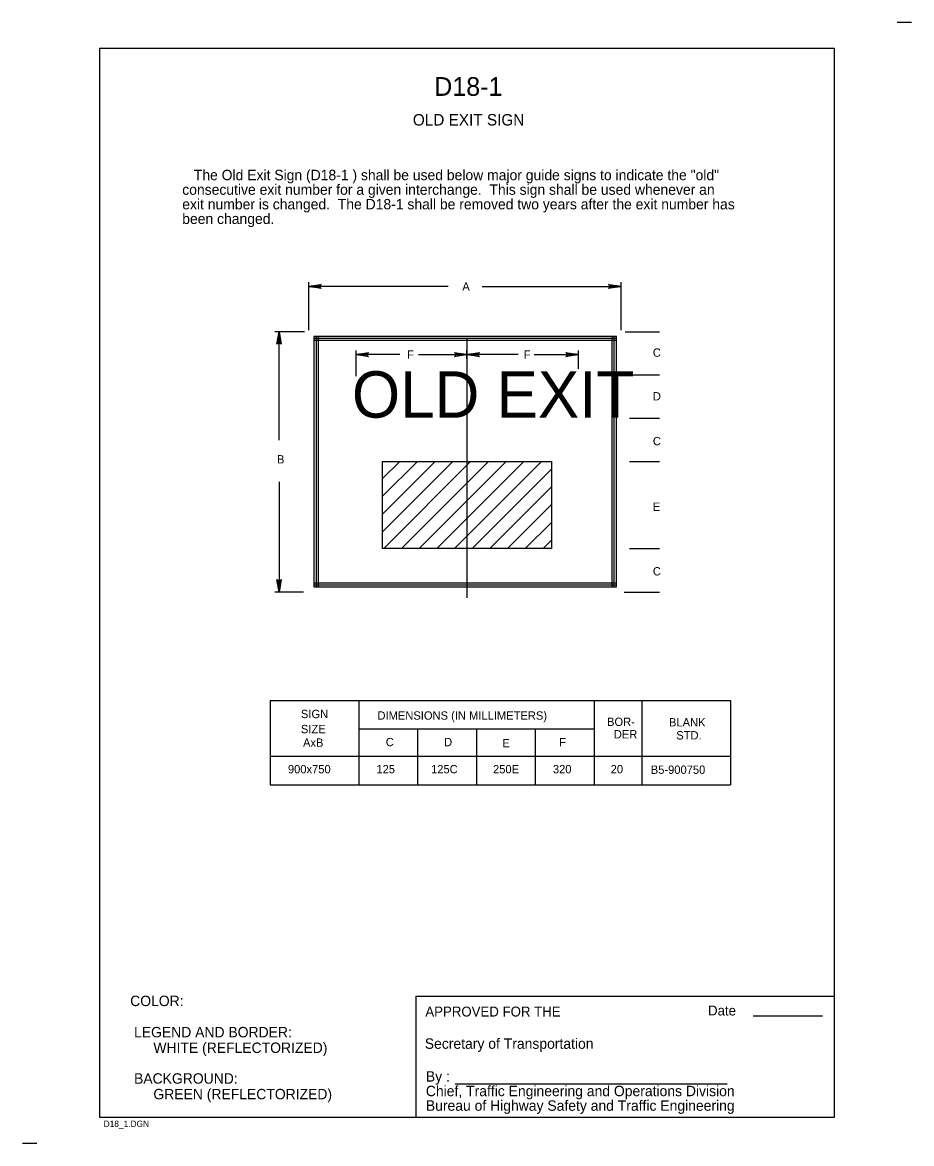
# Model space of a CAD drawing. Extents: x -0.018 to 0.195, y -0.006 to 0.263.
import ezdxf

# ---------------------------------------------------------------- set-up
doc = ezdxf.new("R2010")
doc.units = 0
for name, color, linetype in [('1', 7, 'Continuous'), ('2', 7, 'Continuous'), ('3', 7, 'Continuous')]:
    doc.layers.add(name, color=color, linetype=linetype)

# ---------------------------------------------------------------- blocks, each defined once
blk = doc.blocks.new('RARROW')
at = {"layer": '3'}
for p, q in [((-2.156, 0.285), (-2.2665, 0.384625)), ((-2.2665, 0.384625), (0, 0)), ((0, 0), (-2.2665, -0.379125)), ((-2.156, 0.285), (-2.075625, 0.12075)), ((0, 0), (-2.156, 0.285)), ((-2.14975, -0.2705), (0, 0)), ((-2.075625, 0.12075), (0, 0)), ((0, 0), (-2.074, -0.108)), ((-2.2665, -0.379125), (-2.14975, -0.2705)), ((-2.074, -0.108), (-2.14975, -0.2705))]:
    blk.add_line(p, q, dxfattribs=at)

msp = doc.modelspace()

# ---------------------------------------------------------------- linework, layer by layer
at = {"layer": '1'}
for p, q in [((0.195, 0.26275), (0.1915, 0.26275)), ((0.1765, 0.2565), (0, 0.2565)), ((0, 0.2565), (0, 0)), ((0.1765, 0), (0.1765, 0.2565)), ((0.08825, 0.18675), (0.08825, 0.124625)), ((0.076, 0.029), (0.1765, 0.029)), ((0.076, 0.029), (0.076, 0)), ((0.157, 0.02425), (0.173625, 0.02425)), ((0.085375, 0.008), (0.15075, 0.008)), ((0, 0), (0.1765, 0)), ((-0.015, -0.006375), (-0.0185, -0.006375))]:
    msp.add_line(p, q, dxfattribs=at)
at = {"layer": '3'}
for p, q in [((0.05025, 0.188875), (0.05025, 0.200375)), ((0.08375, 0.199375), (0.05025, 0.199375)), ((0.091875, 0.199375), (0.12525, 0.199375)), ((0.12525, 0.188875), (0.12525, 0.200375)), ((0.04925, 0.1885), (0.042125, 0.1885)), ((0.043125, 0.1625), (0.043125, 0.1885)), ((0.12625, 0.1885), (0.1345, 0.1885)), ((0.0515, 0.187375), (0.0515, 0.12725)), ((0.124125, 0.187375), (0.0515, 0.187375)), ((0.124125, 0.186875), (0.0515, 0.186875)), ((0.124125, 0.186375), (0.0515, 0.186375)), ((0.052, 0.187375), (0.052, 0.12725)), ((0.0525, 0.187375), (0.0525, 0.12725)), ((0.123125, 0.12725), (0.123125, 0.187375)), ((0.123625, 0.12725), (0.123625, 0.187375)), ((0.124125, 0.12725), (0.124125, 0.187375)), ((0.061625, 0.177875), (0.061625, 0.184)), ((0.08825, 0.182), (0.08825, 0.184)), ((0.115, 0.179625), (0.115, 0.184)), ((0.072125, 0.183), (0.061625, 0.183)), ((0.076625, 0.183), (0.08825, 0.183)), ((0.1005, 0.183), (0.08825, 0.183)), ((0.104375, 0.183), (0.115, 0.183)), ((0.12725, 0.178125), (0.1345, 0.178125)), ((0.12725, 0.16775), (0.1345, 0.16775)), ((0.068, 0.15325), (0.072125, 0.157375)), ((0.068, 0.149), (0.076375, 0.157375)), ((0.068, 0.14475), (0.080625, 0.157375)), ((0.068, 0.1405), (0.084875, 0.157375)), ((0.068, 0.1365), (0.068, 0.157375)), ((0.068, 0.157375), (0.1085, 0.157375)), ((0.06825, 0.1365), (0.089125, 0.157375)), ((0.0725, 0.1365), (0.093375, 0.157375)), ((0.07675, 0.1365), (0.097625, 0.157375)), ((0.081, 0.1365), (0.101875, 0.157375)), ((0.08525, 0.1365), (0.106125, 0.157375)), ((0.1085, 0.157375), (0.1085, 0.1365)), ((0.12725, 0.157375), (0.1345, 0.157375)), ((0.0895, 0.1365), (0.1085, 0.1555)), ((0.043125, 0.1525), (0.043125, 0.126)), ((0.09375, 0.1365), (0.1085, 0.15125)), ((0.098, 0.1365), (0.1085, 0.147)), ((0.10225, 0.1365), (0.1085, 0.14275)), ((0.1065, 0.1365), (0.1085, 0.1385)), ((0.1085, 0.1365), (0.068, 0.1365)), ((0.12725, 0.1365), (0.1345, 0.1365)), ((0.0515, 0.12825), (0.124125, 0.12825)), ((0.0515, 0.12775), (0.124125, 0.12775)), ((0.0515, 0.12725), (0.124125, 0.12725)), ((0.049, 0.126), (0.042125, 0.126)), ((0.126, 0.126), (0.1345, 0.126)), ((0.041, 0.1), (0.1515, 0.1)), ((0.041, 0.1), (0.041, 0.07975)), ((0.06225, 0.1), (0.06225, 0.07975)), ((0.11875, 0.1), (0.11875, 0.07975)), ((0.13025, 0.1), (0.13025, 0.07975)), ((0.1515, 0.1), (0.1515, 0.07975)), ((0.11875, 0.093125), (0.06225, 0.093125)), ((0.076375, 0.093125), (0.076375, 0.07975)), ((0.0905, 0.093125), (0.0905, 0.07975)), ((0.104625, 0.093125), (0.104625, 0.07975)), ((0.041, 0.086625), (0.1515, 0.086625)), ((0.041, 0.07975), (0.1515, 0.07975))]:
    msp.add_line(p, q, dxfattribs=at)

# ---------------------------------------------------------------- block references
at = {"layer": '3', "xscale": 0.0013236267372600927, "yscale": 0.001309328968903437}
for p, rotation in [((0.05025, 0.199375), 180), ((0.043125, 0.1885), 90), ((0.061625, 0.183), 180), ((0.08825, 0.183), 180), ((0.043125, 0.126), -90)]:
    msp.add_blockref('RARROW', p, dxfattribs=dict(at, rotation=rotation))
for p in [(0.12525, 0.199375), (0.08825, 0.183), (0.115, 0.183)]:
    msp.add_blockref('RARROW', p, dxfattribs=at)

# ---------------------------------------------------------------- texts
at = {"layer": '1'}
for s, height, p in [('D18-1', 0.0045, (0.080375, 0.245125)), ('OLD EXIT SIGN', 0.00275025, (0.07525, 0.238)), ('COLOR:', 0.0024998, (0.007375, 0.026625)), ('APPROVED FOR THE', 0.00237525, (0.07825, 0.024125)), ('Date ', 0.0023752, (0.146125, 0.024375)), (' LEGEND AND BORDER:', 0.00249975, (0.007375, 0.019125)), ('Secretary of Transportation', 0.00249975, (0.078125, 0.016375)), ('      WHITE (REFLECTORIZED)', 0.00249975, (0.007375, 0.015375)), ('By :', 0.0024998, (0.078375, 0.0085)), (' BACKGROUND:', 0.00249975, (0.007375, 0.008)), ('      GREEN (REFLECTORIZED)', 0.00249975, (0.007375, 0.00425)), ('Chief, Traffic Engineering and Operations Division', 0.00249975, (0.078375, 0.005)), ('Bureau of Highway Safety and Traffic Engineering', 0.00249975, (0.078375, 0.0015)), ('D18_1.DGN', 0.0015, (0.001, -0.002375))]:
    msp.add_text(s, height=height, dxfattribs=at).set_placement(p)
at = {"layer": '2'}
for s, p in [('   The Old Exit Sign (D18-1 ) shall be used below major guide signs to indicate the "old"', (0.019875, 0.224875)), ('consecutive exit number for a given interchange.  This sign shall be used whenever an', (0.019875, 0.221375)), ('exit number is changed.  The D18-1 shall be removed two years after the exit number has', (0.019875, 0.217875)), ('been changed.', (0.019875, 0.214375))]:
    msp.add_text(s, height=0.00249975, dxfattribs=at).set_placement(p)
at = {"layer": '3'}
for s, height, p in [('A', 0.002, (0.087125, 0.198375)), ('F', 0.002, (0.073875, 0.182)), ('F', 0.002, (0.101875, 0.182)), ('C', 0.002, (0.132875, 0.1825)), ('OLD EXIT', 0.0111248, (0.060625, 0.167875)), ('D', 0.002, (0.132875, 0.172)), ('C', 0.002, (0.132875, 0.16125)), ('B', 0.002, (0.042625, 0.156875)), ('E', 0.002, (0.132875, 0.1455)), ('C', 0.002, (0.132875, 0.13)), ('SIGN', 0.0020002, (0.048375, 0.09575)), ('DIMENSIONS (IN MILLIMETERS)', 0.00200025, (0.06675, 0.095375)), ('BOR-', 0.0020002, (0.121875, 0.093875)), ('BLANK', 0.0020002, (0.13675, 0.09375)), ('SIZE', 0.0020002, (0.048375, 0.092125)), ('DER', 0.0020002, (0.1235, 0.090875)), ('STD.', 0.0020002, (0.1385, 0.090625)), ('AxB', 0.0020002, (0.048875, 0.088875)), ('C', 0.002, (0.06875, 0.089)), ('D', 0.002, (0.08275, 0.089)), ('E', 0.002, (0.09675, 0.08875)), ('F', 0.002, (0.110375, 0.089)), ('900x750', 0.0020002, (0.04525, 0.0825)), ('125', 0.0020002, (0.0665, 0.0825)), ('125C', 0.0020002, (0.079625, 0.0825)), ('250E', 0.0020002, (0.0945, 0.0825)), ('320', 0.0020002, (0.108875, 0.0825)), ('20', 0.0020002, (0.12275, 0.0825)), ('B5-900750', 0.0020002, (0.132375, 0.082375))]:
    msp.add_text(s, height=height, dxfattribs=at).set_placement(p)

doc.saveas('drawing.dxf')
